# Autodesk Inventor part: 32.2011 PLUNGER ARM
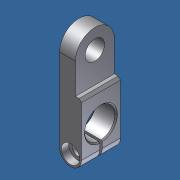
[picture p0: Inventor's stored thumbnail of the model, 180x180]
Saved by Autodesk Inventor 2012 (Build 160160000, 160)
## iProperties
Created: 2016-09
Part Number: 32.2011 PLUNGER ARM
Material: Default
Document SubType Name: Modeling
Designer: Admin
Density: 1 g/cm^3
Author: Admin
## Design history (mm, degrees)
feature "Base1"
body "Solid1"
